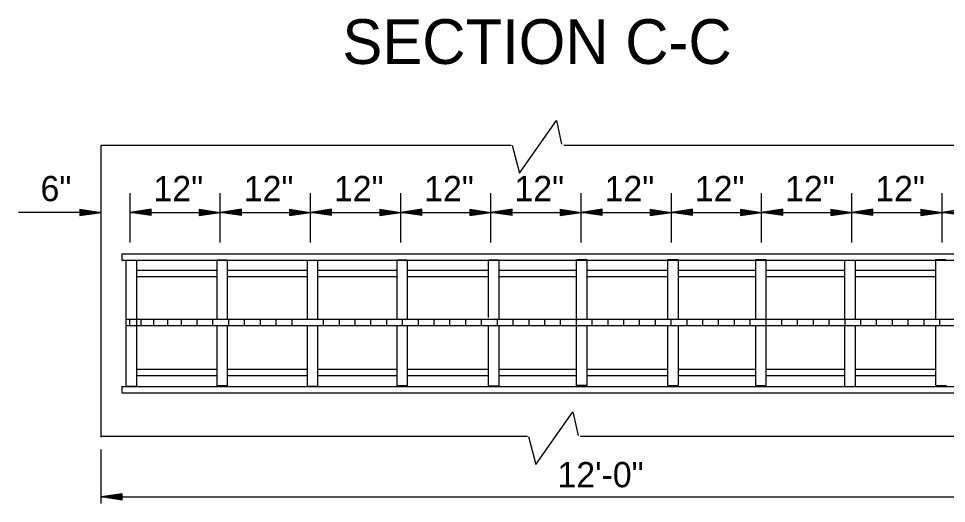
# Model space of a CAD drawing. Extents: x 1375738 to 1375905, y 380661 to 380875.
# Drawn here: x 1375749.28 to 1375765.86, y 380791.56 to 380800.23 of the extents above; entities that cross this region are included whole.
import ezdxf

# ---------------------------------------------------------------- set-up
doc = ezdxf.new("R2010")
doc.units = 0
doc.layers.add('R_Draft', color=7, linetype='Continuous')

msp = doc.modelspace()

# ---------------------------------------------------------------- linework, layer by layer
at = {"layer": 'R_Draft'}
for p, q in [((1375750.756, 380792.747), (1375750.756, 380797.97)), ((1375750.756, 380797.97), (1375758.082, 380797.97)), ((1375759.021, 380797.97), (1375769.46, 380797.97)), ((1375751.276, 380796.231), (1375751.276, 380797.112)), ((1375752.887, 380796.231), (1375752.887, 380797.112)), ((1375754.499, 380796.231), (1375754.499, 380797.112)), ((1375756.11, 380796.231), (1375756.11, 380797.112)), ((1375757.722, 380796.231), (1375757.722, 380797.112)), ((1375759.334, 380796.231), (1375759.334, 380797.112)), ((1375760.945, 380796.231), (1375760.945, 380797.112)), ((1375762.557, 380796.231), (1375762.557, 380797.112)), ((1375764.168, 380796.231), (1375764.168, 380797.112)), ((1375765.78, 380796.231), (1375765.78, 380797.112)), ((1375750.756, 380796.765), (1375749.283, 380796.765)), ((1375750.379, 380796.822), (1375750.756, 380796.765)), ((1375750.379, 380796.822), (1375750.379, 380796.709)), ((1375750.379, 380796.813), (1375750.693, 380796.765)), ((1375750.379, 380796.803), (1375750.628, 380796.765)), ((1375750.379, 380796.793), (1375750.566, 380796.765)), ((1375750.379, 380796.783), (1375750.502, 380796.765)), ((1375750.379, 380796.774), (1375750.439, 380796.765)), ((1375750.379, 380796.709), (1375750.756, 380796.765)), ((1375750.379, 380796.747), (1375750.502, 380796.765)), ((1375750.379, 380796.728), (1375750.628, 380796.765)), ((1375750.379, 380796.718), (1375750.693, 380796.765)), ((1375750.379, 380796.738), (1375750.566, 380796.765)), ((1375750.379, 380796.757), (1375750.439, 380796.765)), ((1375751.652, 380796.822), (1375751.276, 380796.765)), ((1375751.276, 380796.765), (1375752.887, 380796.765)), ((1375751.652, 380796.709), (1375751.276, 380796.765)), ((1375751.652, 380796.813), (1375751.338, 380796.765)), ((1375751.652, 380796.718), (1375751.338, 380796.765)), ((1375751.652, 380796.803), (1375751.403, 380796.765)), ((1375751.652, 380796.728), (1375751.403, 380796.765)), ((1375751.652, 380796.793), (1375751.466, 380796.765)), ((1375751.652, 380796.738), (1375751.466, 380796.765)), ((1375751.652, 380796.784), (1375751.53, 380796.765)), ((1375751.652, 380796.747), (1375751.53, 380796.765)), ((1375751.652, 380796.774), (1375751.592, 380796.765)), ((1375751.652, 380796.757), (1375751.592, 380796.765)), ((1375751.652, 380796.709), (1375751.652, 380796.822)), ((1375752.51, 380796.822), (1375752.887, 380796.765)), ((1375752.51, 380796.822), (1375752.51, 380796.709)), ((1375752.51, 380796.813), (1375752.824, 380796.765)), ((1375752.51, 380796.803), (1375752.76, 380796.765)), ((1375752.51, 380796.793), (1375752.697, 380796.765)), ((1375752.51, 380796.783), (1375752.633, 380796.765)), ((1375752.51, 380796.774), (1375752.57, 380796.765)), ((1375752.51, 380796.709), (1375752.887, 380796.765)), ((1375752.51, 380796.747), (1375752.633, 380796.765)), ((1375752.51, 380796.728), (1375752.76, 380796.765)), ((1375752.51, 380796.718), (1375752.824, 380796.765)), ((1375752.51, 380796.738), (1375752.697, 380796.765)), ((1375752.51, 380796.757), (1375752.57, 380796.765)), ((1375753.263, 380796.822), (1375752.887, 380796.765)), ((1375752.887, 380796.765), (1375754.499, 380796.765)), ((1375753.263, 380796.709), (1375752.887, 380796.765)), ((1375753.263, 380796.813), (1375752.95, 380796.765)), ((1375753.263, 380796.718), (1375752.95, 380796.765)), ((1375753.263, 380796.803), (1375753.014, 380796.765)), ((1375753.263, 380796.728), (1375753.014, 380796.765)), ((1375753.263, 380796.793), (1375753.077, 380796.765)), ((1375753.263, 380796.738), (1375753.077, 380796.765)), ((1375753.263, 380796.784), (1375753.141, 380796.765)), ((1375753.263, 380796.747), (1375753.141, 380796.765)), ((1375753.263, 380796.774), (1375753.204, 380796.765)), ((1375753.263, 380796.757), (1375753.204, 380796.765)), ((1375753.263, 380796.709), (1375753.263, 380796.822)), ((1375754.122, 380796.822), (1375754.499, 380796.765)), ((1375754.122, 380796.822), (1375754.122, 380796.709)), ((1375754.122, 380796.813), (1375754.436, 380796.765)), ((1375754.122, 380796.803), (1375754.371, 380796.765)), ((1375754.122, 380796.793), (1375754.308, 380796.765)), ((1375754.122, 380796.783), (1375754.244, 380796.765)), ((1375754.122, 380796.774), (1375754.182, 380796.765)), ((1375754.122, 380796.709), (1375754.499, 380796.765)), ((1375754.122, 380796.747), (1375754.244, 380796.765)), ((1375754.122, 380796.728), (1375754.371, 380796.765)), ((1375754.122, 380796.718), (1375754.436, 380796.765)), ((1375754.122, 380796.738), (1375754.308, 380796.765)), ((1375754.122, 380796.757), (1375754.182, 380796.765)), ((1375754.875, 380796.822), (1375754.499, 380796.765)), ((1375754.499, 380796.765), (1375756.11, 380796.765)), ((1375754.875, 380796.709), (1375754.499, 380796.765)), ((1375754.875, 380796.813), (1375754.562, 380796.765)), ((1375754.875, 380796.718), (1375754.562, 380796.765)), ((1375754.875, 380796.803), (1375754.626, 380796.765)), ((1375754.875, 380796.728), (1375754.626, 380796.765)), ((1375754.875, 380796.793), (1375754.689, 380796.765)), ((1375754.875, 380796.738), (1375754.689, 380796.765)), ((1375754.875, 380796.784), (1375754.753, 380796.765)), ((1375754.875, 380796.747), (1375754.753, 380796.765)), ((1375754.875, 380796.774), (1375754.816, 380796.765)), ((1375754.875, 380796.757), (1375754.816, 380796.765)), ((1375754.875, 380796.709), (1375754.875, 380796.822)), ((1375755.734, 380796.822), (1375756.11, 380796.765)), ((1375755.734, 380796.822), (1375755.734, 380796.709)), ((1375755.734, 380796.813), (1375756.048, 380796.765)), ((1375755.734, 380796.803), (1375755.983, 380796.765)), ((1375755.734, 380796.793), (1375755.92, 380796.765)), ((1375755.734, 380796.783), (1375755.856, 380796.765)), ((1375755.734, 380796.774), (1375755.794, 380796.765)), ((1375755.734, 380796.709), (1375756.11, 380796.765)), ((1375755.734, 380796.747), (1375755.856, 380796.765)), ((1375755.734, 380796.728), (1375755.983, 380796.765)), ((1375755.734, 380796.718), (1375756.048, 380796.765)), ((1375755.734, 380796.738), (1375755.92, 380796.765)), ((1375755.734, 380796.757), (1375755.794, 380796.765)), ((1375756.486, 380796.822), (1375756.11, 380796.765)), ((1375756.486, 380796.709), (1375756.11, 380796.765)), ((1375756.11, 380796.765), (1375757.722, 380796.765)), ((1375756.486, 380796.813), (1375756.173, 380796.765)), ((1375756.486, 380796.718), (1375756.173, 380796.765)), ((1375756.486, 380796.803), (1375756.238, 380796.765)), ((1375756.486, 380796.728), (1375756.238, 380796.765)), ((1375756.486, 380796.793), (1375756.3, 380796.765)), ((1375756.486, 380796.738), (1375756.3, 380796.765)), ((1375756.486, 380796.784), (1375756.364, 380796.765)), ((1375756.486, 380796.747), (1375756.364, 380796.765)), ((1375756.486, 380796.774), (1375756.427, 380796.765)), ((1375756.486, 380796.757), (1375756.427, 380796.765)), ((1375756.486, 380796.709), (1375756.486, 380796.822)), ((1375757.346, 380796.822), (1375757.722, 380796.765)), ((1375757.346, 380796.822), (1375757.346, 380796.709)), ((1375757.346, 380796.813), (1375757.659, 380796.765)), ((1375757.346, 380796.803), (1375757.594, 380796.765)), ((1375757.346, 380796.793), (1375757.532, 380796.765)), ((1375757.346, 380796.783), (1375757.468, 380796.765)), ((1375757.346, 380796.774), (1375757.405, 380796.765)), ((1375757.346, 380796.709), (1375757.722, 380796.765)), ((1375757.346, 380796.747), (1375757.468, 380796.765)), ((1375757.346, 380796.728), (1375757.594, 380796.765)), ((1375757.346, 380796.718), (1375757.659, 380796.765)), ((1375757.346, 380796.738), (1375757.532, 380796.765)), ((1375757.346, 380796.757), (1375757.405, 380796.765)), ((1375758.098, 380796.822), (1375757.722, 380796.765)), ((1375758.098, 380796.709), (1375757.722, 380796.765)), ((1375757.722, 380796.765), (1375759.334, 380796.765)), ((1375758.098, 380796.813), (1375757.785, 380796.765)), ((1375758.098, 380796.718), (1375757.785, 380796.765)), ((1375758.098, 380796.803), (1375757.85, 380796.765)), ((1375758.098, 380796.728), (1375757.85, 380796.765)), ((1375758.098, 380796.793), (1375757.912, 380796.765)), ((1375758.098, 380796.738), (1375757.912, 380796.765)), ((1375758.098, 380796.784), (1375757.976, 380796.765)), ((1375758.098, 380796.747), (1375757.976, 380796.765)), ((1375758.098, 380796.774), (1375758.039, 380796.765)), ((1375758.098, 380796.757), (1375758.039, 380796.765)), ((1375758.098, 380796.709), (1375758.098, 380796.822)), ((1375758.957, 380796.822), (1375759.334, 380796.765)), ((1375758.957, 380796.822), (1375758.957, 380796.709)), ((1375758.957, 380796.813), (1375759.271, 380796.765)), ((1375758.957, 380796.803), (1375759.206, 380796.765)), ((1375758.957, 380796.793), (1375759.144, 380796.765)), ((1375758.957, 380796.783), (1375759.079, 380796.765)), ((1375758.957, 380796.774), (1375759.016, 380796.765)), ((1375758.957, 380796.709), (1375759.334, 380796.765)), ((1375758.957, 380796.747), (1375759.079, 380796.765)), ((1375758.957, 380796.728), (1375759.206, 380796.765)), ((1375758.957, 380796.718), (1375759.271, 380796.765)), ((1375758.957, 380796.738), (1375759.144, 380796.765)), ((1375758.957, 380796.757), (1375759.016, 380796.765)), ((1375759.71, 380796.822), (1375759.334, 380796.765)), ((1375759.71, 380796.709), (1375759.334, 380796.765)), ((1375759.334, 380796.765), (1375760.945, 380796.765)), ((1375759.71, 380796.813), (1375759.396, 380796.765)), ((1375759.71, 380796.718), (1375759.396, 380796.765)), ((1375759.71, 380796.803), (1375759.461, 380796.765)), ((1375759.71, 380796.728), (1375759.461, 380796.765)), ((1375759.71, 380796.793), (1375759.523, 380796.765)), ((1375759.71, 380796.738), (1375759.523, 380796.765)), ((1375759.71, 380796.784), (1375759.587, 380796.765)), ((1375759.71, 380796.747), (1375759.587, 380796.765)), ((1375759.71, 380796.774), (1375759.65, 380796.765)), ((1375759.71, 380796.757), (1375759.65, 380796.765)), ((1375759.71, 380796.709), (1375759.71, 380796.822)), ((1375760.568, 380796.822), (1375760.945, 380796.765)), ((1375760.568, 380796.822), (1375760.568, 380796.709)), ((1375760.568, 380796.813), (1375760.882, 380796.765)), ((1375760.568, 380796.803), (1375760.817, 380796.765)), ((1375760.568, 380796.793), (1375760.755, 380796.765)), ((1375760.568, 380796.783), (1375760.691, 380796.765)), ((1375760.568, 380796.774), (1375760.628, 380796.765)), ((1375760.568, 380796.709), (1375760.945, 380796.765)), ((1375760.568, 380796.747), (1375760.691, 380796.765)), ((1375760.568, 380796.728), (1375760.817, 380796.765)), ((1375760.568, 380796.718), (1375760.882, 380796.765)), ((1375760.568, 380796.738), (1375760.755, 380796.765)), ((1375760.568, 380796.757), (1375760.628, 380796.765)), ((1375761.321, 380796.822), (1375760.945, 380796.765)), ((1375761.321, 380796.709), (1375760.945, 380796.765)), ((1375760.945, 380796.765), (1375762.557, 380796.765)), ((1375761.321, 380796.813), (1375761.008, 380796.765)), ((1375761.321, 380796.718), (1375761.008, 380796.765)), ((1375761.321, 380796.803), (1375761.072, 380796.765)), ((1375761.321, 380796.728), (1375761.072, 380796.765)), ((1375761.321, 380796.793), (1375761.135, 380796.765)), ((1375761.321, 380796.738), (1375761.135, 380796.765)), ((1375761.321, 380796.784), (1375761.199, 380796.765)), ((1375761.321, 380796.747), (1375761.199, 380796.765)), ((1375761.321, 380796.774), (1375761.262, 380796.765)), ((1375761.321, 380796.757), (1375761.262, 380796.765)), ((1375761.321, 380796.709), (1375761.321, 380796.822)), ((1375762.18, 380796.822), (1375762.557, 380796.765)), ((1375762.18, 380796.822), (1375762.18, 380796.709)), ((1375762.18, 380796.813), (1375762.494, 380796.765)), ((1375762.18, 380796.803), (1375762.429, 380796.765)), ((1375762.18, 380796.793), (1375762.366, 380796.765)), ((1375762.18, 380796.783), (1375762.302, 380796.765)), ((1375762.18, 380796.774), (1375762.24, 380796.765)), ((1375762.18, 380796.709), (1375762.557, 380796.765)), ((1375762.18, 380796.747), (1375762.302, 380796.765)), ((1375762.18, 380796.728), (1375762.429, 380796.765)), ((1375762.18, 380796.718), (1375762.494, 380796.765)), ((1375762.18, 380796.738), (1375762.366, 380796.765)), ((1375762.18, 380796.757), (1375762.24, 380796.765)), ((1375762.933, 380796.822), (1375762.557, 380796.765)), ((1375762.557, 380796.765), (1375764.168, 380796.765)), ((1375762.933, 380796.709), (1375762.557, 380796.765)), ((1375762.933, 380796.813), (1375762.62, 380796.765)), ((1375762.933, 380796.718), (1375762.62, 380796.765)), ((1375762.933, 380796.803), (1375762.684, 380796.765)), ((1375762.933, 380796.728), (1375762.684, 380796.765)), ((1375762.933, 380796.793), (1375762.747, 380796.765)), ((1375762.933, 380796.738), (1375762.747, 380796.765)), ((1375762.933, 380796.784), (1375762.81, 380796.765)), ((1375762.933, 380796.747), (1375762.81, 380796.765)), ((1375762.933, 380796.774), (1375762.873, 380796.765)), ((1375762.933, 380796.757), (1375762.873, 380796.765)), ((1375762.933, 380796.709), (1375762.933, 380796.822)), ((1375763.792, 380796.822), (1375764.168, 380796.765)), ((1375763.792, 380796.822), (1375763.792, 380796.709)), ((1375763.792, 380796.813), (1375764.105, 380796.765)), ((1375763.792, 380796.803), (1375764.04, 380796.765)), ((1375763.792, 380796.793), (1375763.978, 380796.765)), ((1375763.792, 380796.783), (1375763.914, 380796.765)), ((1375763.792, 380796.774), (1375763.851, 380796.765)), ((1375763.792, 380796.709), (1375764.168, 380796.765)), ((1375763.792, 380796.747), (1375763.914, 380796.765)), ((1375763.792, 380796.728), (1375764.04, 380796.765)), ((1375763.792, 380796.718), (1375764.105, 380796.765)), ((1375763.792, 380796.738), (1375763.978, 380796.765)), ((1375763.792, 380796.757), (1375763.851, 380796.765)), ((1375764.544, 380796.822), (1375764.168, 380796.765)), ((1375764.168, 380796.765), (1375765.78, 380796.765)), ((1375764.544, 380796.709), (1375764.168, 380796.765)), ((1375764.544, 380796.813), (1375764.231, 380796.765)), ((1375764.544, 380796.718), (1375764.231, 380796.765)), ((1375764.544, 380796.803), (1375764.296, 380796.765)), ((1375764.544, 380796.728), (1375764.296, 380796.765)), ((1375764.544, 380796.793), (1375764.358, 380796.765)), ((1375764.544, 380796.738), (1375764.358, 380796.765)), ((1375764.544, 380796.784), (1375764.422, 380796.765)), ((1375764.544, 380796.747), (1375764.422, 380796.765)), ((1375764.544, 380796.774), (1375764.485, 380796.765)), ((1375764.544, 380796.757), (1375764.485, 380796.765)), ((1375764.544, 380796.709), (1375764.544, 380796.822)), ((1375765.404, 380796.822), (1375765.78, 380796.765)), ((1375765.404, 380796.822), (1375765.404, 380796.709)), ((1375765.404, 380796.813), (1375765.717, 380796.765)), ((1375765.404, 380796.803), (1375765.652, 380796.765)), ((1375765.404, 380796.793), (1375765.59, 380796.765)), ((1375765.404, 380796.783), (1375765.526, 380796.765)), ((1375765.404, 380796.774), (1375765.463, 380796.765)), ((1375765.404, 380796.709), (1375765.78, 380796.765)), ((1375765.404, 380796.747), (1375765.526, 380796.765)), ((1375765.404, 380796.728), (1375765.652, 380796.765)), ((1375765.404, 380796.718), (1375765.717, 380796.765)), ((1375765.404, 380796.738), (1375765.59, 380796.765)), ((1375765.404, 380796.757), (1375765.463, 380796.765)), ((1375766.156, 380796.822), (1375765.78, 380796.765)), ((1375765.78, 380796.765), (1375767.391, 380796.765)), ((1375766.156, 380796.709), (1375765.78, 380796.765)), ((1375766.156, 380796.813), (1375765.843, 380796.765)), ((1375766.156, 380796.718), (1375765.843, 380796.765)), ((1375751.127, 380796.025), (1375769.258, 380796.025)), ((1375751.127, 380796.025), (1375751.127, 380795.912)), ((1375760.882, 380795.926), (1375761.06, 380795.926)), ((1375760.882, 380794.863), (1375760.882, 380795.926)), ((1375761.07, 380794.863), (1375761.07, 380795.926)), ((1375762.453, 380794.863), (1375762.453, 380795.926)), ((1375762.454, 380795.926), (1375762.631, 380795.926)), ((1375762.641, 380794.863), (1375762.641, 380795.926)), ((1375765.672, 380795.926), (1375765.85, 380795.926)), ((1375765.672, 380794.863), (1375765.672, 380795.926)), ((1375751.127, 380795.912), (1375769.258, 380795.912)), ((1375755.988, 380795.917), (1375755.988, 380795.919)), ((1375757.681, 380795.919), (1375757.863, 380795.919)), ((1375757.681, 380794.889), (1375757.681, 380795.919)), ((1375757.869, 380794.855), (1375757.869, 380795.919)), ((1375764.045, 380794.849), (1375764.045, 380795.912)), ((1375764.046, 380795.912), (1375764.223, 380795.912)), ((1375764.233, 380794.849), (1375764.233, 380795.912)), ((1375751.383, 380795.731), (1375752.829, 380795.731)), ((1375751.383, 380795.618), (1375752.829, 380795.618)), ((1375753.01, 380795.731), (1375754.435, 380795.731)), ((1375753.01, 380795.618), (1375754.435, 380795.618)), ((1375754.616, 380795.731), (1375756.048, 380795.731)), ((1375754.616, 380795.618), (1375756.048, 380795.618)), ((1375756.228, 380795.731), (1375757.678, 380795.731)), ((1375756.228, 380795.618), (1375757.678, 380795.618)), ((1375757.871, 380795.731), (1375759.252, 380795.731)), ((1375757.876, 380795.618), (1375759.252, 380795.618)), ((1375759.433, 380795.731), (1375760.882, 380795.731)), ((1375759.433, 380795.618), (1375760.882, 380795.618)), ((1375761.07, 380795.731), (1375762.453, 380795.731)), ((1375761.07, 380795.618), (1375762.453, 380795.618)), ((1375762.641, 380795.731), (1375764.045, 380795.731)), ((1375762.641, 380795.618), (1375764.045, 380795.618)), ((1375764.233, 380795.731), (1375765.672, 380795.731)), ((1375764.233, 380795.618), (1375765.672, 380795.618)), ((1375751.202, 380794.857), (1375769.16, 380794.857)), ((1375751.27, 380794.751), (1375751.27, 380794.853)), ((1375751.472, 380794.751), (1375751.472, 380794.853)), ((1375751.698, 380794.751), (1375751.698, 380794.853)), ((1375751.952, 380794.751), (1375751.952, 380794.853)), ((1375752.192, 380794.751), (1375752.192, 380794.853)), ((1375752.474, 380794.751), (1375752.474, 380794.853)), ((1375752.756, 380794.751), (1375752.756, 380794.853)), ((1375753.039, 380794.751), (1375753.039, 380794.853)), ((1375753.321, 380794.751), (1375753.321, 380794.853)), ((1375753.603, 380794.751), (1375753.603, 380794.853)), ((1375753.886, 380794.751), (1375753.886, 380794.853)), ((1375754.168, 380794.751), (1375754.168, 380794.853)), ((1375754.732, 380794.751), (1375754.732, 380794.853)), ((1375755.015, 380794.751), (1375755.015, 380794.853)), ((1375755.297, 380794.751), (1375755.297, 380794.853)), ((1375755.579, 380794.751), (1375755.579, 380794.853)), ((1375755.861, 380794.751), (1375755.861, 380794.853)), ((1375756.144, 380794.751), (1375756.144, 380794.853)), ((1375756.426, 380794.751), (1375756.426, 380794.853)), ((1375756.708, 380794.751), (1375756.708, 380794.853)), ((1375756.99, 380794.751), (1375756.99, 380794.853)), ((1375757.273, 380794.751), (1375757.273, 380794.853)), ((1375757.555, 380794.751), (1375757.555, 380794.853)), ((1375757.838, 380794.751), (1375757.838, 380794.853)), ((1375758.12, 380794.751), (1375758.12, 380794.853)), ((1375758.402, 380794.751), (1375758.402, 380794.853)), ((1375758.684, 380794.751), (1375758.684, 380794.853)), ((1375758.966, 380794.751), (1375758.966, 380794.853)), ((1375759.248, 380794.751), (1375759.248, 380794.853)), ((1375759.531, 380794.751), (1375759.531, 380794.853)), ((1375759.813, 380794.751), (1375759.813, 380794.853)), ((1375760.096, 380794.751), (1375760.096, 380794.853)), ((1375760.378, 380794.751), (1375760.378, 380794.853)), ((1375760.66, 380794.751), (1375760.66, 380794.853)), ((1375760.942, 380794.751), (1375760.942, 380794.853)), ((1375761.225, 380794.751), (1375761.225, 380794.853)), ((1375761.507, 380794.751), (1375761.507, 380794.853)), ((1375761.789, 380794.751), (1375761.789, 380794.853)), ((1375762.071, 380794.751), (1375762.071, 380794.853)), ((1375762.354, 380794.751), (1375762.354, 380794.853)), ((1375762.636, 380794.751), (1375762.636, 380794.853)), ((1375762.918, 380794.751), (1375762.918, 380794.853)), ((1375763.2, 380794.751), (1375763.2, 380794.853)), ((1375763.483, 380794.751), (1375763.483, 380794.853)), ((1375763.765, 380794.751), (1375763.765, 380794.853)), ((1375764.047, 380794.751), (1375764.047, 380794.853)), ((1375764.33, 380794.751), (1375764.33, 380794.853)), ((1375764.612, 380794.751), (1375764.612, 380794.853)), ((1375764.894, 380794.751), (1375764.894, 380794.853)), ((1375765.176, 380794.751), (1375765.176, 380794.853)), ((1375765.458, 380794.751), (1375765.458, 380794.853)), ((1375765.741, 380794.751), (1375765.741, 380794.853)), ((1375751.202, 380794.744), (1375769.16, 380794.744)), ((1375757.681, 380793.662), (1375757.681, 380794.737)), ((1375757.869, 380793.85), (1375757.869, 380794.731)), ((1375760.882, 380793.669), (1375760.882, 380794.751)), ((1375761.07, 380793.669), (1375761.07, 380794.751)), ((1375762.453, 380793.669), (1375762.453, 380794.751)), ((1375762.641, 380793.669), (1375762.641, 380794.751)), ((1375764.045, 380793.655), (1375764.045, 380794.737)), ((1375764.233, 380793.655), (1375764.233, 380794.737)), ((1375765.672, 380793.669), (1375765.672, 380794.751)), ((1375751.383, 380793.963), (1375752.829, 380793.963)), ((1375753.01, 380793.963), (1375754.435, 380793.963)), ((1375754.616, 380793.963), (1375756.048, 380793.963)), ((1375756.228, 380793.963), (1375757.678, 380793.963)), ((1375757.871, 380793.963), (1375759.252, 380793.963)), ((1375759.433, 380793.963), (1375760.882, 380793.963)), ((1375761.07, 380793.963), (1375762.453, 380793.963)), ((1375762.641, 380793.963), (1375764.045, 380793.963)), ((1375764.233, 380793.963), (1375765.672, 380793.963)), ((1375751.383, 380793.85), (1375752.829, 380793.85)), ((1375753.01, 380793.85), (1375754.435, 380793.85)), ((1375754.616, 380793.85), (1375756.048, 380793.85)), ((1375756.228, 380793.85), (1375757.678, 380793.85)), ((1375757.869, 380793.85), (1375759.252, 380793.85)), ((1375757.869, 380793.662), (1375757.869, 380793.844)), ((1375759.433, 380793.85), (1375760.882, 380793.85)), ((1375761.07, 380793.85), (1375762.453, 380793.85)), ((1375762.641, 380793.85), (1375764.045, 380793.85)), ((1375764.233, 380793.85), (1375765.672, 380793.85)), ((1375751.127, 380793.655), (1375769.258, 380793.655)), ((1375751.127, 380793.655), (1375751.127, 380793.542)), ((1375757.684, 380793.662), (1375757.867, 380793.662)), ((1375760.888, 380793.669), (1375761.068, 380793.669)), ((1375762.458, 380793.669), (1375762.639, 380793.669)), ((1375764.051, 380793.655), (1375764.231, 380793.655)), ((1375765.677, 380793.669), (1375765.858, 380793.669)), ((1375751.127, 380793.542), (1375769.258, 380793.542)), ((1375750.756, 380792.765), (1375758.377, 380792.765)), ((1375759.316, 380792.765), (1375769.46, 380792.765)), ((1375750.756, 380791.561), (1375750.756, 380792.525)), ((1375751.132, 380791.735), (1375750.756, 380791.679)), ((1375750.756, 380791.679), (1375769.46, 380791.679)), ((1375751.132, 380791.622), (1375750.756, 380791.679)), ((1375751.132, 380791.725), (1375750.818, 380791.679)), ((1375751.132, 380791.632), (1375750.818, 380791.679)), ((1375751.132, 380791.716), (1375750.883, 380791.679)), ((1375751.132, 380791.641), (1375750.883, 380791.679)), ((1375751.132, 380791.707), (1375750.946, 380791.679)), ((1375751.132, 380791.651), (1375750.946, 380791.679)), ((1375751.132, 380791.697), (1375751.01, 380791.679)), ((1375751.132, 380791.66), (1375751.01, 380791.679)), ((1375751.132, 380791.687), (1375751.073, 380791.679)), ((1375751.132, 380791.67), (1375751.073, 380791.679)), ((1375751.132, 380791.622), (1375751.132, 380791.735))]:
    msp.add_line(p, q, dxfattribs=at)
for points in [[(1375758.1, 380797.966), (1375758.229, 380797.468), (1375758.892, 380798.407), (1375758.984, 380797.984)], [(1375759.252, 380794.857), (1375759.252, 380795.926), (1375759.433, 380795.926), (1375759.433, 380794.857)], [(1375752.829, 380794.857), (1375752.829, 380795.919), (1375753.01, 380795.919), (1375753.01, 380794.857)], [(1375754.442, 380794.857), (1375754.442, 380795.912), (1375754.622, 380795.912), (1375754.622, 380794.857)], [(1375756.048, 380794.857), (1375756.048, 380795.919), (1375756.228, 380795.919), (1375756.228, 380794.857)], [(1375753.01, 380794.744), (1375753.01, 380793.662), (1375752.829, 380793.662), (1375752.829, 380794.744)], [(1375754.622, 380794.744), (1375754.622, 380793.655), (1375754.442, 380793.655), (1375754.442, 380794.744)], [(1375756.228, 380794.744), (1375756.228, 380793.662), (1375756.048, 380793.662), (1375756.048, 380794.744)], [(1375759.433, 380794.744), (1375759.433, 380793.669), (1375759.252, 380793.669), (1375759.252, 380794.744)], [(1375758.395, 380792.756), (1375758.524, 380792.259), (1375759.186, 380793.198), (1375759.279, 380792.774)]]:
    msp.add_lwpolyline(points, dxfattribs=at)
msp.add_lwpolyline([(1375751.208, 380795.912), (1375751.39, 380795.912), (1375751.39, 380793.655), (1375751.208, 380793.655)], close=True, dxfattribs=at)

# ---------------------------------------------------------------- texts
for s, height, p in [('SECTION C-C', 0.8, (1375755.068, 380799.421)), ('6"', 0.4516, (1375749.676, 380796.967)), ('12"', 0.4516, (1375751.695, 380796.967)), ('12"', 0.4516, (1375753.307, 380796.967)), ('12"', 0.4516, (1375754.918, 380796.967)), ('12"', 0.4516, (1375756.53, 380796.967)), ('12"', 0.4516, (1375758.142, 380796.967)), ('12"', 0.4516, (1375759.753, 380796.967)), ('12"', 0.4516, (1375761.365, 380796.967)), ('12"', 0.4516, (1375762.976, 380796.967)), ('12"', 0.4516, (1375764.588, 380796.967)), ('12\'-0"', 0.4516, (1375758.911, 380791.851))]:
    msp.add_text(s, height=height, dxfattribs=at).set_placement(p)

doc.saveas('drawing.dxf')
